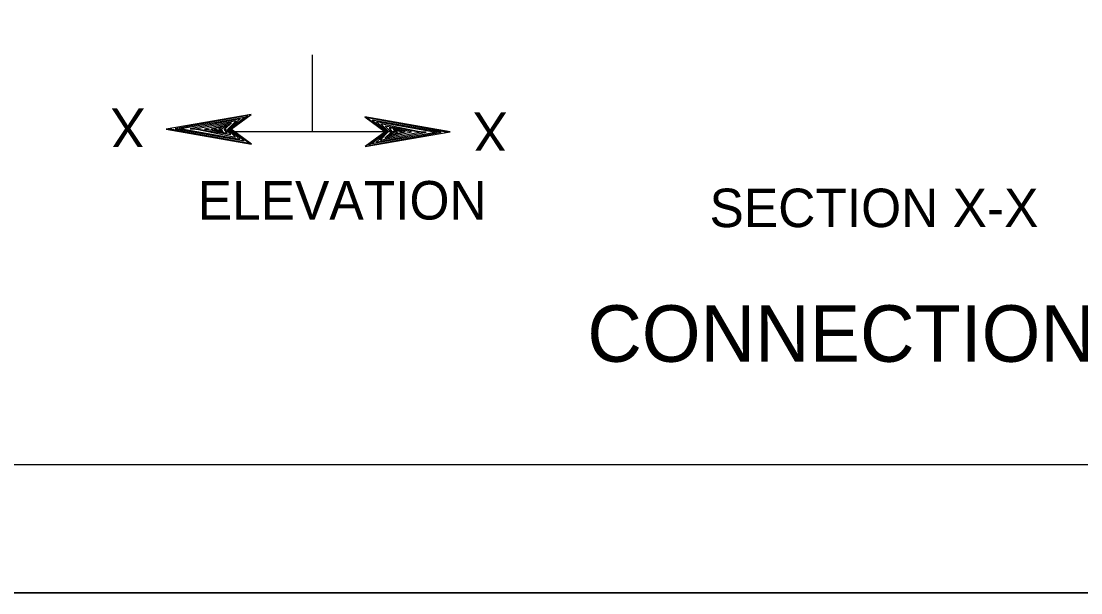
# Model space of a CAD drawing. Extents: x 499866 to 500993, y 499985 to 500645.
# Drawn here: x 500569.8 to 500693.7, y 499985 to 500051.8 of the extents above; entities that cross this region are included whole.
import ezdxf

# ---------------------------------------------------------------- set-up
doc = ezdxf.new("R2010")
doc.units = 0
for name, color, linetype in [('1', 7, 'Continuous'), ('2', 7, 'Continuous'), ('41', 7, 'Continuous'), ('5', 7, 'Continuous')]:
    doc.layers.add(name, color=color, linetype=linetype)

msp = doc.modelspace()

# ---------------------------------------------------------------- linework, layer by layer
at = {"layer": '1'}
for p, q in [((500000, 500000), (500990, 500000)), ((499944.83, 499985), (500993, 499985))]:
    msp.add_line(p, q, dxfattribs=at)
at = {"layer": '2'}
msp.add_line((500603.84, 500047.91), (500603.84, 500038.9), dxfattribs=at)
at = {"layer": '41'}
msp.add_lwpolyline([(499944.83, 500645), (500993, 500645), (500993, 499985), (499944.83, 499985)], close=True, dxfattribs=at)
at = {"layer": '5'}
for p, q in [((500603.84, 500038.9), (500593.85, 500038.9)), ((500613.83, 500038.9), (500603.84, 500038.9))]:
    msp.add_line(p, q, dxfattribs=at)
for points in [[(500586.81, 500039.2), (500596.78, 500037.43), (500594.4, 500039.2), (500596.73, 500040.93), (500586.81, 500039.2), (500587.47, 500039.22), (500596.5, 500037.56), (500594.21, 500039.22), (500596.33, 500040.8), (500587.83, 500039.25), (500588.16, 500039.2), (500595.9, 500037.82), (500594.16, 500039.22), (500595.95, 500040.57), (500588.31, 500039.2), (500588.64, 500039.25), (500595.41, 500038.03), (500594.09, 500039.2), (500595.43, 500040.41), (500589.61, 500039.25), (500590.17, 500039.25), (500594.9, 500038.28), (500593.98, 500039.17), (500594.98, 500040.16), (500590.27, 500039.2), (500590.8, 500039.17), (500594.36, 500038.56), (500593.68, 500039.25), (500594.42, 500039.93), (500591.29, 500039.2), (500591.79, 500039.15), (500593.93, 500038.74), (500593.58, 500039.22), (500594.16, 500039.75), (500592.06, 500039.2), (500593.45, 500038.87), (500593.25, 500039.25), (500593.86, 500039.63), (500592.41, 500039.25), (500593.32, 500039.02), (500592.94, 500039.32), (500593.38, 500039.5), (500592.94, 500039.22), (500593.17, 500039.17)], [(500619.97, 500038.9), (500610, 500040.66), (500612.38, 500038.9), (500610.05, 500037.16), (500619.97, 500038.9), (500619.3, 500038.88), (500610.27, 500040.53), (500612.56, 500038.87), (500610.45, 500037.3), (500618.95, 500038.85), (500618.61, 500038.9), (500610.88, 500040.27), (500612.62, 500038.88), (500610.83, 500037.52), (500618.46, 500038.9), (500618.13, 500038.85), (500611.37, 500040.07), (500612.69, 500038.9), (500611.34, 500037.68), (500617.17, 500038.85), (500616.61, 500038.85), (500611.87, 500039.82), (500612.79, 500038.92), (500611.8, 500037.93), (500616.51, 500038.9), (500615.97, 500038.93), (500612.41, 500039.54), (500613.1, 500038.84), (500612.36, 500038.16), (500615.48, 500038.9), (500614.98, 500038.95), (500612.84, 500039.35), (500613.2, 500038.87), (500612.61, 500038.34), (500614.72, 500038.9), (500613.33, 500039.23), (500613.53, 500038.85), (500612.92, 500038.46), (500614.37, 500038.84), (500613.46, 500039.07), (500613.84, 500038.77), (500613.4, 500038.59), (500613.84, 500038.87), (500613.61, 500038.92)]]:
    msp.add_lwpolyline(points, dxfattribs=at)

# ---------------------------------------------------------------- texts
for p in [(500584.33, 500041.62), (500626.68, 500041.17)]:
    msp.add_text('X', height=4.5, rotation=180, dxfattribs=at).set_placement(p)
for s, height, p in [('ELEVATION', 4.5, (500590.48, 500028.64)), ('SECTION X-X', 4.5, (500650.3, 500027.75)), ('CONNECTION KEY', 6.6001, (500636.02, 500012.01))]:
    msp.add_text(s, height=height, dxfattribs=at).set_placement(p)

doc.saveas('drawing.dxf')
